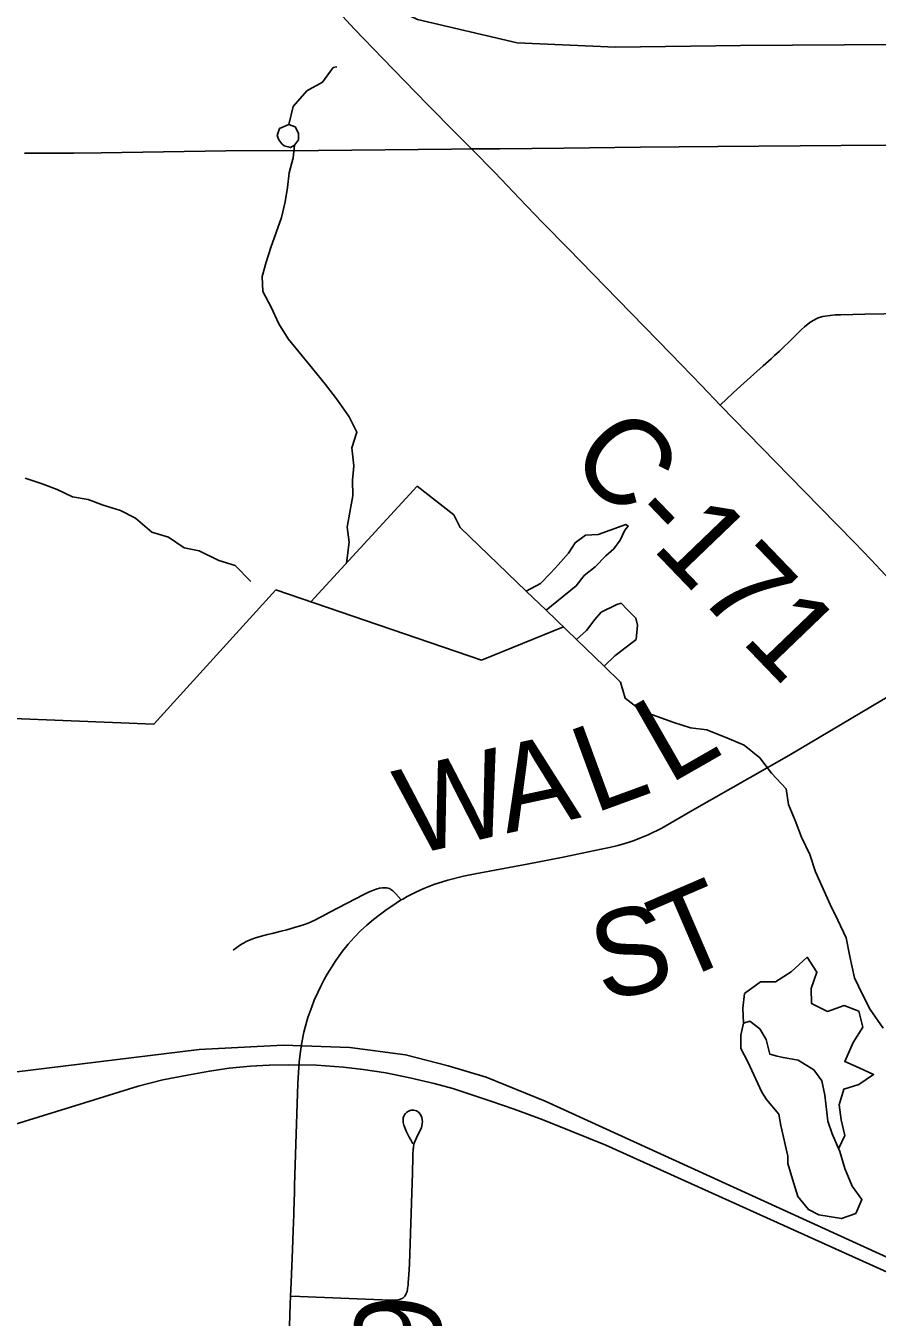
# Model space of a CAD drawing. Extents: x 0 to 34, y 0 to 22.
# Drawn here: x 6.327 to 6.886, y 15.105 to 15.953 of the extents above; entities that cross this region are included whole.
import ezdxf

# ---------------------------------------------------------------- set-up
doc = ezdxf.new("R2010")
doc.units = 0
for name, color, linetype in [('GM_X_County_Road', 7, 'Continuous'), ('GM_X_County_Road_Text', 7, 'Continuous'), ('GM_X_Minor_Lake', 7, 'Continuous'), ('GM_X_Minor_River', 7, 'Continuous'), ('GM_X_Rail_Line', 7, 'Continuous'), ('GM_X_Township_Road', 7, 'Continuous'), ('SH_Text', 7, 'Continuous')]:
    doc.layers.add(name, color=color, linetype=linetype)

msp = doc.modelspace()

# ---------------------------------------------------------------- linework, layer by layer
at = {"layer": 'GM_X_County_Road'}
for points in [[(6.61999, 15.87248), (6.60999, 15.88265), (6.59119, 15.90161), (6.57606, 15.91717), (6.56178, 15.93189), (6.54315, 15.95108), (6.5327, 15.96251), (6.53052, 15.96512), (6.52794, 15.9685), (6.52592, 15.97148), (6.52447, 15.97373), (6.5233, 15.97579), (6.5223, 15.97804), (6.52149, 15.9804), (6.521, 15.98243), (6.52067, 15.98451), (6.52045, 15.98844)], [(6.61999, 15.87248), (6.63855, 15.87263), (6.68061, 15.87296), (6.73106, 15.87368), (6.78164, 15.87402), (6.86269, 15.87472), (6.92117, 15.87519), (6.96434, 15.87513)], [(6.32652, 15.86976), (6.35878, 15.86965), (6.37673, 15.86994), (6.45858, 15.87112), (6.5195, 15.87138), (6.60684, 15.87238), (6.61999, 15.87248)], [(6.78337, 15.7043), (6.77127, 15.71696), (6.7509, 15.73793), (6.73351, 15.7557), (6.71617, 15.77351), (6.69962, 15.79035), (6.68363, 15.80689), (6.66665, 15.8242), (6.6516, 15.83986), (6.63528, 15.85695), (6.61999, 15.87248)], [(6.88235, 15.60259), (6.87147, 15.61411), (6.84879, 15.63715), (6.82874, 15.65755), (6.78337, 15.7043)], [(6.90987, 15.57376), (6.89187, 15.59251), (6.88235, 15.60259)], [(6.76495, 15.43798), (6.82839, 15.47419), (6.88931, 15.51026), (6.90052, 15.51687)], [(6.57377, 15.37932), (6.57481, 15.3799), (6.57763, 15.38154), (6.58351, 15.38449), (6.5887, 15.3869), (6.59531, 15.38941), (6.60444, 15.39238), (6.61472, 15.39485), (6.62237, 15.39643), (6.63189, 15.3982), (6.65755, 15.40303), (6.6801, 15.40751), (6.70524, 15.41265), (6.71069, 15.41386), (6.71613, 15.41515), (6.72002, 15.4162), (6.72347, 15.41729), (6.72682, 15.41846), (6.73054, 15.41989), (6.73595, 15.42216), (6.74496, 15.42657), (6.76495, 15.43798)], [(6.52169, 15.36848), (6.52697, 15.37139), (6.54923, 15.38295), (6.55241, 15.38445), (6.55571, 15.38584), (6.55797, 15.38664), (6.55964, 15.38707), (6.56145, 15.38729), (6.56214, 15.38735), (6.56334, 15.38735), (6.56398, 15.38732), (6.56518, 15.3871), (6.56654, 15.38655), (6.56708, 15.38622), (6.56825, 15.38524), (6.5702, 15.38325), (6.57377, 15.37932)], [(6.50343, 15.17916), (6.50373, 15.18934), (6.50381, 15.19179), (6.50465, 15.21909), (6.50595, 15.25884), (6.50679, 15.27307), (6.5076, 15.27987), (6.50853, 15.28567), (6.50994, 15.29253), (6.51256, 15.30205), (6.51506, 15.30918), (6.51672, 15.31344), (6.51896, 15.31858), (6.52093, 15.32268), (6.52319, 15.327), (6.52518, 15.3305), (6.52819, 15.33541), (6.53099, 15.33966), (6.53521, 15.34561), (6.53899, 15.35023), (6.54295, 15.35474), (6.54702, 15.35898), (6.55125, 15.36279), (6.55564, 15.36649), (6.56023, 15.37008), (6.56379, 15.37271), (6.56654, 15.37465), (6.56953, 15.37667), (6.57137, 15.37785), (6.57377, 15.37932)], [(6.46348, 15.34634), (6.46578, 15.34809), (6.46769, 15.34945), (6.46946, 15.35057), (6.4707, 15.35125), (6.47207, 15.35196), (6.47306, 15.35242), (6.47566, 15.35351), (6.47822, 15.35445), (6.48058, 15.35514), (6.48262, 15.35569), (6.48609, 15.35659), (6.48908, 15.35733), (6.49499, 15.35877), (6.49879, 15.35977), (6.50375, 15.36115), (6.50745, 15.36227), (6.51038, 15.3633), (6.51276, 15.3642), (6.51473, 15.36497), (6.51706, 15.36603), (6.51993, 15.36751), (6.52169, 15.36848)], [(6.50108, 15.11915), (6.50147, 15.12821), (6.50249, 15.14992), (6.50296, 15.16233), (6.50328, 15.17283), (6.50337, 15.17712), (6.50343, 15.17916)], [(6.49446, 14.91825), (6.4951, 14.93904), (6.4982, 15.01735), (6.49978, 15.07235), (6.50008, 15.08477), (6.50086, 15.11397), (6.50108, 15.11915)]]:
    msp.add_lwpolyline(points, dxfattribs=at)
at = {"layer": 'GM_X_Minor_Lake'}
for p, q in [((6.49339, 15.87854), (6.49549, 15.87588)), ((6.65598, 15.58208), (6.66892, 15.56959)), ((6.68884, 15.55036), (6.707, 15.53284)), ((6.82303, 15.23121), (6.82772, 15.21114))]:
    msp.add_line(p, q, dxfattribs=at)
for points in [[(6.49549, 15.87588), (6.49704, 15.8745), (6.49969, 15.87376), (6.50121, 15.87339), (6.50385, 15.87493), (6.50647, 15.87836), (6.50643, 15.88291), (6.50413, 15.88706), (6.49996, 15.88855), (6.49392, 15.88585), (6.49244, 15.88129), (6.49339, 15.87854)], [(6.66892, 15.56959), (6.68872, 15.58548), (6.69396, 15.59234), (6.70111, 15.59809), (6.70824, 15.60534), (6.7135, 15.60994), (6.71762, 15.61566), (6.7206, 15.62213), (6.72285, 15.6248), (6.72132, 15.62592), (6.71114, 15.62205), (6.70321, 15.61934), (6.69489, 15.61889), (6.68811, 15.61391), (6.68363, 15.60705), (6.67687, 15.59942), (6.67199, 15.59407), (6.66523, 15.58719), (6.65598, 15.58208)], [(6.707, 15.53284), (6.71409, 15.53963), (6.72161, 15.54538), (6.72801, 15.55036), (6.72907, 15.55985), (6.7279, 15.56439), (6.72218, 15.57003), (6.71836, 15.57418), (6.71534, 15.5734), (6.70516, 15.56839), (6.70104, 15.56342), (6.69541, 15.55618), (6.68884, 15.55036)], [(6.82772, 15.21114), (6.82776, 15.20621), (6.83087, 15.196), (6.83436, 15.18465), (6.84124, 15.17598), (6.84808, 15.17262), (6.86286, 15.17008), (6.8723, 15.17356), (6.87639, 15.1827), (6.86989, 15.19137), (6.86525, 15.20309), (6.86176, 15.21406), (6.85675, 15.22578), (6.85404, 15.2341), (6.85201, 15.25115), (6.85005, 15.26062), (6.84469, 15.26778), (6.83442, 15.27415), (6.82457, 15.27597), (6.82078, 15.2767), (6.81585, 15.27818), (6.8135, 15.28764), (6.80929, 15.29481), (6.80281, 15.2997), (6.79866, 15.29853), (6.79683, 15.29055), (6.79689, 15.28183), (6.8015, 15.27314), (6.81074, 15.25311), (6.81381, 15.2482), (6.82183, 15.23878), (6.82303, 15.23121)]]:
    msp.add_lwpolyline(points, dxfattribs=at)
at = {"layer": 'GM_X_Minor_River'}
for p, q in [((6.58433, 15.65107), (6.51452, 15.57498)), ((6.60832, 15.6323), (6.58433, 15.65107)), ((6.61255, 15.62399), (6.60832, 15.6323)), ((6.65598, 15.58208), (6.61255, 15.62399)), ((6.41146, 15.49465), (6.49138, 15.58286)), ((6.49138, 15.58286), (6.62648, 15.53687)), ((6.68884, 15.55036), (6.66892, 15.56959)), ((6.62648, 15.53687), (6.68034, 15.55857)), ((6.71781, 15.52241), (6.707, 15.53284)), ((6.0408, 15.50961), (6.41146, 15.49465))]:
    msp.add_line(p, q, dxfattribs=at)
for points in [[(6.49996, 15.88855), (6.50289, 15.90033), (6.51189, 15.91063), (6.52207, 15.9164), (6.52918, 15.92593), (6.53145, 15.92633)], [(6.53791, 15.60047), (6.53958, 15.61432), (6.53837, 15.62417), (6.54018, 15.63405), (6.54199, 15.64468), (6.54191, 15.65492), (6.5426, 15.6644), (6.54137, 15.67615), (6.54469, 15.68641), (6.53969, 15.69661), (6.53204, 15.70755), (6.52401, 15.71772), (6.5156, 15.72828), (6.49955, 15.74787), (6.49342, 15.75768), (6.48841, 15.76864), (6.48303, 15.77884), (6.48258, 15.78869), (6.48515, 15.79819), (6.4881, 15.80769), (6.49181, 15.81758), (6.49514, 15.82747), (6.49771, 15.83772), (6.49914, 15.84721), (6.50021, 15.8567), (6.50278, 15.86658), (6.5037, 15.87485)], [(6.47507, 15.58842), (6.46476, 15.59896), (6.45414, 15.60229), (6.44122, 15.60864), (6.43137, 15.61046), (6.42109, 15.61758), (6.41009, 15.62091), (6.39942, 15.62993), (6.38954, 15.63516), (6.37816, 15.63849), (6.36829, 15.6422), (6.35806, 15.64402), (6.3478, 15.64887), (6.33793, 15.65259), (6.32692, 15.65629)], [(6.76384, 15.49242), (6.75284, 15.49575), (6.74183, 15.49984), (6.73158, 15.50355), (6.72092, 15.51181), (6.71781, 15.52241)], [(6.89028, 15.29506), (6.88185, 15.30751), (6.87686, 15.31733), (6.87147, 15.32828), (6.86834, 15.34229), (6.86597, 15.35441), (6.86058, 15.36613), (6.85558, 15.37633), (6.85096, 15.38653), (6.84595, 15.39787), (6.84208, 15.40921), (6.83669, 15.42055), (6.83244, 15.43152), (6.8282, 15.4421), (6.8266, 15.45233), (6.81706, 15.46249), (6.80941, 15.47267), (6.79913, 15.48094), (6.78926, 15.48503), (6.77445, 15.49099), (6.76384, 15.49242)], [(6.79866, 15.29853), (6.7982, 15.30838), (6.79926, 15.31787), (6.8098, 15.32554), (6.81964, 15.32561), (6.82981, 15.33214), (6.84033, 15.3417), (6.84684, 15.33189), (6.84314, 15.32124), (6.84322, 15.31138), (6.85386, 15.30616), (6.8648, 15.31003), (6.87429, 15.30631), (6.87703, 15.29571), (6.87067, 15.28581), (6.86509, 15.27325), (6.87458, 15.26915), (6.88408, 15.26467), (6.87429, 15.25815), (6.86447, 15.25504), (6.86152, 15.24478), (6.86274, 15.23493), (6.86509, 15.2247), (6.86096, 15.21594)]]:
    msp.add_lwpolyline(points, dxfattribs=at)
at = {"layer": 'GM_X_Rail_Line'}
for points in [[(6.24266, 15.25691), (6.44116, 15.28121), (6.49632, 15.28396), (6.54006, 15.28256), (6.57657, 15.27771), (6.60476, 15.27042), (6.62953, 15.26307), (6.66833, 15.24718), (7.07958, 15.05943), (7.18281, 15.00864), (7.27614, 14.96864), (7.31856, 14.9442)], [(6.31698, 15.23103), (6.36577, 15.24617), (6.40103, 15.25696), (6.41729, 15.26114), (6.43356, 15.26436), (6.44789, 15.26694), (6.46077, 15.26887), (6.47478, 15.27016), (6.48718, 15.2708), (6.50006, 15.27113), (6.51825, 15.2708), (6.53597, 15.26952), (6.54885, 15.26807), (6.56366, 15.26581), (6.57944, 15.26259), (6.59538, 15.25889), (6.60778, 15.25551), (6.62082, 15.25116), (6.63258, 15.24729), (6.64804, 15.24198), (6.66639, 15.23522), (6.68539, 15.22749), (6.70826, 15.21831), (6.92644, 15.11993)]]:
    msp.add_lwpolyline(points, dxfattribs=at)
at = {"layer": 'GM_X_Township_Road'}
for points in [[(6.78337, 15.7043), (6.79185, 15.71239), (6.79684, 15.7169), (6.81161, 15.7301), (6.81668, 15.73472), (6.81896, 15.73684), (6.82221, 15.73974), (6.83115, 15.74841), (6.83665, 15.75379), (6.83868, 15.75565), (6.84105, 15.75767), (6.84286, 15.75899), (6.84469, 15.7601), (6.84675, 15.76106), (6.8484, 15.76167), (6.8507, 15.76233), (6.85224, 15.76265), (6.85554, 15.76312), (6.8588, 15.76343), (6.86263, 15.76361), (6.87832, 15.76389), (6.9038, 15.76447)], [(6.57562, 15.11859), (6.57617, 15.11928), (6.57678, 15.12023), (6.5771, 15.12083), (6.57746, 15.12175), (6.57764, 15.12238), (6.57786, 15.1233), (6.57804, 15.12412), (6.57824, 15.12548), (6.57834, 15.12649), (6.57846, 15.12805), (6.57881, 15.13316), (6.57918, 15.14047), (6.58113, 15.20007), (6.58137, 15.21054), (6.58151, 15.21349), (6.58157, 15.21442), (6.58169, 15.21594), (6.58179, 15.21668), (6.58196, 15.21768), (6.58214, 15.21857), (6.58243, 15.21953), (6.583, 15.22124), (6.58376, 15.22304), (6.58436, 15.22429), (6.58632, 15.22803), (6.58706, 15.22984), (6.58737, 15.23093), (6.58764, 15.23247), (6.5877, 15.23378), (6.58767, 15.23504), (6.58744, 15.23649), (6.58659, 15.2385), (6.58524, 15.24007), (6.58389, 15.2409), (6.5821, 15.24134), (6.58033, 15.24125), (6.57867, 15.24075), (6.57729, 15.23988), (6.57637, 15.23892), (6.57594, 15.23826), (6.5755, 15.23739), (6.57516, 15.23628), (6.57506, 15.23555), (6.57502, 15.23414), (6.57512, 15.2332), (6.57525, 15.23234), (6.5755, 15.23146), (6.57592, 15.23027), (6.57631, 15.22931), (6.57737, 15.22704), (6.5791, 15.22366), (6.58003, 15.22193), (6.58154, 15.2193)], [(6.50108, 15.11915), (6.50726, 15.11887), (6.56662, 15.11653), (6.56915, 15.11652), (6.5715, 15.1167), (6.57271, 15.11694), (6.57388, 15.11733), (6.57484, 15.11789), (6.57562, 15.11859)]]:
    msp.add_lwpolyline(points, dxfattribs=at)
at = {"layer": 'SH_Text'}
msp.add_lwpolyline([(6.04363, 16.45614), (6.16219, 16.3439), (6.22585, 16.27897), (6.29975, 16.20287), (6.37745, 16.12252), (6.45878, 16.03908), (6.4804, 16.01858), (6.52045, 15.98844), (6.58451, 15.95751), (6.64988, 15.94219), (6.71462, 15.93934), (6.79663, 15.94028), (7.82198, 15.947)], dxfattribs=at)

# ---------------------------------------------------------------- texts
at = {"layer": 'GM_X_County_Road_Text'}
for s, height, rotation, p in [('C-171', 0.056818, 313.8476, (6.68212, 15.66818)), ('L', 0.05682, 29.8001, (6.74965, 15.4549)), ('L', 0.05682, 20.13301, (6.70026, 15.43585)), ('A', 0.05682, 12.10366, (6.64302, 15.42295)), ('W', 0.05682, 13.04915, (6.57913, 15.40814)), ('T', 0.05682, 23.31254, (6.75423, 15.32445)), ('S', 0.05682, 12.67517, (6.70589, 15.31249)), ('C-159', 0.056818, 87.9948, (6.59364, 14.91205))]:
    msp.add_text(s, height=height, rotation=rotation, dxfattribs=at).set_placement(p)

doc.saveas('drawing.dxf')
